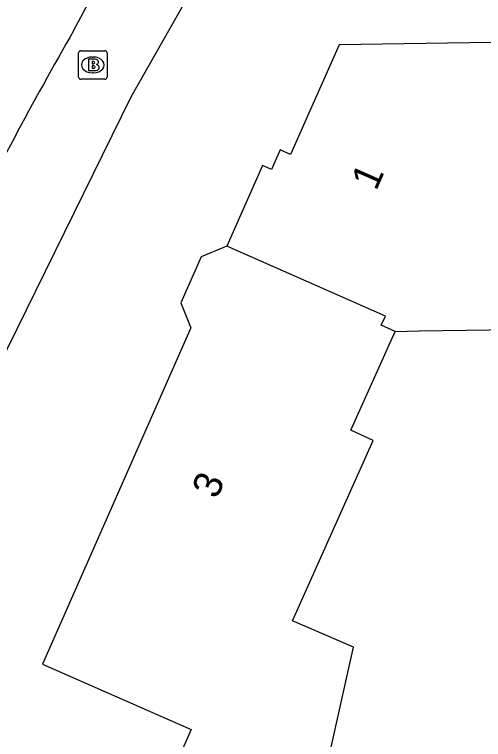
# Model space of a CAD drawing. Extents: x 161354 to 161876, y 382161 to 382804.
# Drawn here: x 161438.54 to 161455.04, y 382620.3 to 382645.82 of the extents above; entities that cross this region are included whole.
import ezdxf

# ---------------------------------------------------------------- set-up
doc = ezdxf.new("R2010")
doc.units = 0
for name, color, linetype in [('IMGEO_Brandkraan', 7, 'Continuous'), ('IMGEO_Pand', 7, 'Continuous'), ('IMGEO_Pand_nummerreeks', 7, 'Continuous'), ('IMGEO_Rijbaan_lokaal_open', 7, 'Continuous'), ('IMGEO_Voetpad_open', 7, 'Continuous')]:
    doc.layers.add(name, color=color, linetype=linetype)

msp = doc.modelspace()

# ---------------------------------------------------------------- linework, layer by layer
at = {"layer": 'IMGEO_Brandkraan'}
for p, q in [((161440.8, 382643.62), (161440.8, 382644.472)), ((161440.875, 382644.546), (161441.727, 382644.546)), ((161441.801, 382644.472), (161441.801, 382643.62)), ((161441.288, 382644.326), (161441.313, 382644.326)), ((161441.311, 382643.766), (161441.286, 382643.766)), ((161441.727, 382643.546), (161440.875, 382643.546))]:
    msp.add_line(p, q, dxfattribs=at)
for points in [[(161440.8, 382643.62), (161440.8, 382644.472)], [(161440.875, 382644.546), (161441.727, 382644.546)], [(161441.801, 382644.472), (161441.801, 382643.62)], [(161441.148, 382644.246), (161441.148, 382643.846), (161441.361, 382643.846)], [(161441.379, 382644.246), (161441.148, 382644.246)], [(161441.327, 382644.165), (161441.273, 382644.165), (161441.273, 382644.089)], [(161441.273, 382644.089), (161441.326, 382644.089)], [(161441.335, 382644.013), (161441.273, 382644.013), (161441.273, 382643.932)], [(161441.273, 382643.932), (161441.335, 382643.932)], [(161441.727, 382643.546), (161440.875, 382643.546)]]:
    msp.add_lwpolyline(points, dxfattribs=at)
for centre, radius, start, end in [((161440.877, 382644.47), 0.0765, 91.552, 178.448), ((161440.877, 382644.47), 0.0765, 91.552, 178.448), ((161441.725, 382644.47), 0.0765, 1.552, 88.448), ((161441.725, 382644.47), 0.0765, 1.552, 88.448), ((161441.383, 382644.101), 0.145, 59.4692, 91.5367), ((161441.408, 382644.148), 0.0922, 285.5137, 58.1501), ((161441.328, 382644.127), 0.0379, 267.8285, 90.9355), ((161441.336, 382643.972), 0.0404, 269.8759, 90.5077), ((161441.413, 382643.956), 0.105, 301.3115, 78.989), ((161441.367, 382644.097), 0.251, 268.6676, 293.5347), ((161440.877, 382643.622), 0.0765, 181.552, 268.448), ((161440.877, 382643.622), 0.0765, 181.552, 268.448), ((161441.725, 382643.622), 0.0765, 271.552, 358.448), ((161441.725, 382643.622), 0.0765, 271.552, 358.448)]:
    msp.add_arc(centre, radius, start, end, dxfattribs=at)
for centre, major_axis, ratio, start_param, end_param in [((161441.287, 382644.046), (-0.387, 0.002), 0.722429, 4.712389, 7.853982), ((161441.312, 382644.046), (-0.39, 0.002), 0.717154, 1.570796, 4.712389)]:
    msp.add_ellipse(centre, major_axis=major_axis, ratio=ratio, start_param=start_param, end_param=end_param, dxfattribs=at)
at = {"layer": 'IMGEO_Pand'}
for points in [[(161460.766, 382641.821), (161460.352, 382642.48), (161460.008, 382642.264), (161458.361, 382644.885), (161449.962, 382644.759), (161448.257, 382640.892), (161447.89, 382641.054), (161447.585, 382640.362), (161447.266, 382640.503), (161446.013, 382637.661)], [(161446.013, 382637.661), (161445.106, 382637.288), (161444.392, 382635.668), (161444.747, 382634.789), (161439.528, 382622.948), (161444.755, 382620.644), (161443.467, 382617.72), (161448.278, 382616.356), (161449.421, 382616.032), (161450.3, 382619.131), (161449.527, 382619.35), (161450.469, 382623.549), (161448.319, 382624.476), (161451.167, 382630.827), (161450.373, 382631.183), (161451.936, 382634.668)], [(161451.936, 382634.668), (161451.446, 382634.884), (161451.593, 382635.204), (161446.013, 382637.661)], [(161451.936, 382634.668), (161452.78, 382634.681), (161456.914, 382634.742)]]:
    msp.add_lwpolyline(points, dxfattribs=at)
at = {"layer": 'IMGEO_Rijbaan_lokaal_open'}
msp.add_lwpolyline([(161440.623, 382645.247), (161442.203, 382648.213), (161443.233, 382649.912), (161443.351, 382650.129)], dxfattribs=at)
msp.add_arc((161554.26, 382579.852), 131.11, 150.08102, 153.86205, dxfattribs=at)
at = {"layer": 'IMGEO_Voetpad_open'}
msp.add_lwpolyline([(161459.276, 382654.164), (161449.465, 382654.844), (161447.977, 382652.326), (161442.636, 382642.916), (161437.607, 382632.685), (161435.473, 382627.706), (161432.284, 382616.838), (161429.648, 382602.151), (161428.735, 382591.734), (161428.36, 382584.865), (161428.803, 382579.556), (161430.088, 382568.58), (161430.881, 382563.561), (161434.555, 382551.436), (161439.58, 382538.533), (161443.443, 382529.747)], dxfattribs=at)

# ---------------------------------------------------------------- texts
at = {"layer": 'IMGEO_Pand_nummerreeks'}
for s, rotation, p in [('1', 66.2053, (161451.267, 382639.588)), ('3', 66.211, (161445.661, 382628.73))]:
    msp.add_text(s, height=1, rotation=rotation, dxfattribs=at).set_placement(p)

doc.saveas('drawing.dxf')
